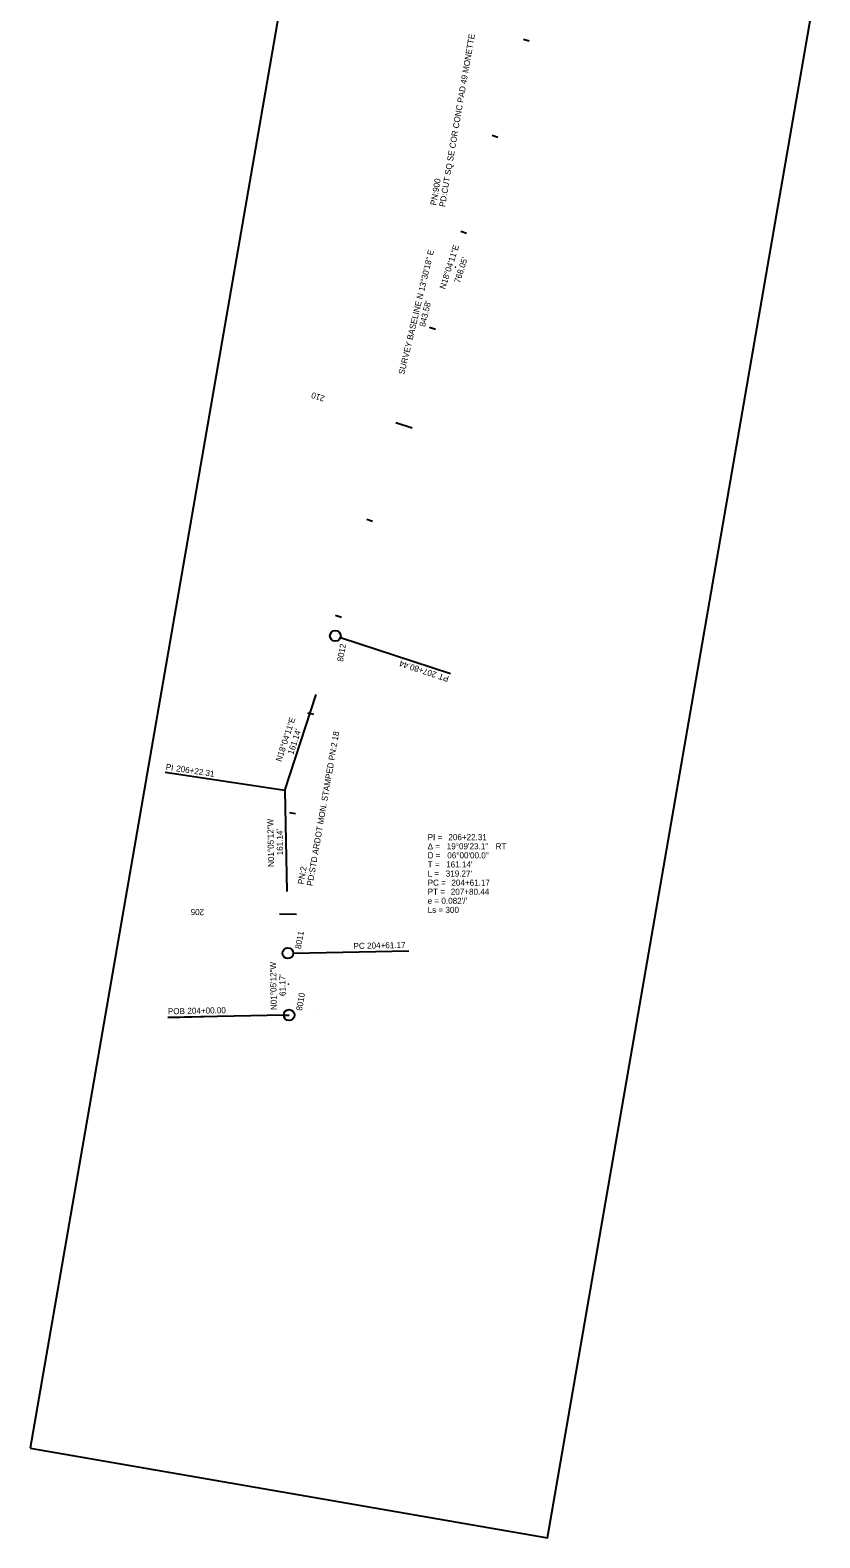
# Model space of a CAD drawing. Extents: x 1802363 to 1804577, y 572235 to 575339.
# Drawn here: x 1802947 to 1803729, y 572235 to 573728 of the extents above; entities that cross this region are included whole.
import ezdxf

# ---------------------------------------------------------------- set-up
doc = ezdxf.new("R2010")
doc.units = 0
for name, color, linetype in [('_CIVIL_CONSTRUCTION', 7, 'Continuous'), ('DSN_DRFT_Named-Boundary', 7, 'Continuous'), ('DSN_RDWY_Alignment Annotation', 7, 'Continuous'), ('DSN_ROW_Point-Annotation', 7, 'Continuous'), ('S_BASELINE_ANNOT', 7, 'Continuous'), ('S_PRIMARY_CTL_ANNOT', 7, 'Continuous')]:
    doc.layers.add(name, color=color, linetype=linetype)

msp = doc.modelspace()

# ---------------------------------------------------------------- linework, layer by layer
at = {"layer": '_CIVIL_CONSTRUCTION'}
for centre in [(1803368.1, 573493.4), (1803368.1, 573493.4), (1803368.1, 573493.4), (1803202.6, 572783.4)]:
    msp.add_circle(centre, 0.05, dxfattribs=at)
at = {"layer": 'DSN_DRFT_Named-Boundary'}
msp.add_line((1803231.8, 572753.4), (1803231.8, 572753.4), dxfattribs=at)
msp.add_lwpolyline([(1802946.7, 572323.9), (1803459.1, 572235.1), (1803729, 573792.9), (1803216.7, 573881.7)], close=True, dxfattribs=at)
at = {"layer": 'DSN_RDWY_Alignment Annotation'}
for p, q in [((1803435.4, 573719.1), (1803441.1, 573717.3)), ((1803404.4, 573624.1), (1803410.1, 573622.2)), ((1803373.4, 573529), (1803379.1, 573527.1)), ((1803342.4, 573433.9), (1803348.1, 573432.1)), ((1803309.1, 573339.6), (1803325, 573334.4)), ((1803280.3, 573243.8), (1803286, 573241.9)), ((1803249.3, 573148.7), (1803255, 573146.9)), ((1803249, 573128.3), (1803249, 573128.3)), ((1803254, 573126.6), (1803363, 573091.1)), ((1803363, 573091.1), (1803363, 573091.1)), ((1803199, 572975.1), (1803230, 573070.2)), ((1803221.4, 573052.2), (1803227.3, 573050.8)), ((1803199, 572975.1), (1803080.3, 572992.8)), ((1803080.3, 572992.8), (1803080.3, 572992.8)), ((1803199, 572975.1), (1803200.9, 572875.1)), ((1803203.5, 572953.2), (1803209.5, 572952.5)), ((1803193.7, 572853), (1803210.5, 572852.6)), ((1803202, 572814), (1803202, 572814)), ((1803207.4, 572814.1), (1803322, 572816.3)), ((1803322, 572816.3), (1803322, 572816.3)), ((1803197.9, 572752.7), (1803083.2, 572750.5)), ((1803083.2, 572750.5), (1803119.2, 572751.2)), ((1803197.2, 572752.7), (1803203.2, 572752.8)), ((1803203.2, 572752.8), (1803203.2, 572752.8))]:
    msp.add_line(p, q, dxfattribs=at)
for centre in [(1803249, 573128.3), (1803202, 572814), (1803203.2, 572752.8)]:
    msp.add_circle(centre, 5.34, dxfattribs=at)

# ---------------------------------------------------------------- texts
for s, rotation, p in [('N18°04\'11"E', 71.9303, (1803357.7, 573471.1)), ('210', 161.9303, (1803239.1, 573365.6)), ('8012', 80.1683, (1803256.6, 573102.4)), ('207+80.44', 161.9303, (1803349.8, 573092.2)), ('PT', 161.9303, (1803362.1, 573088.2)), ('N18°04\'11"E', 71.9303, (1803195.5, 573003.2)), ("161.14'", 71.9303, (1803207.3, 573010.2)), ('PI ', 351.5085, (1803080.7, 572995.8)), ('206+22.31', 351.5085, (1803091.1, 572994.2)), ('N01°05\'12"W', 91.0867, (1803188.4, 572899.5)), ("161.14'", 91.0867, (1803197.2, 572911)), ('205', 178.757, (1803119.1, 572857.6)), ('8011', 80.1683, (1803214.9, 572817.8)), ('204+61.17', 1.0867, (1803280.5, 572818.5)), ('PC', 1.0867, (1803267.1, 572818.2)), ('N01°05\'12"W', 91.0867, (1803191.1, 572757.8)), ("61.17'", 91.0867, (1803199.8, 572771.7)), ('8010', 80.1683, (1803216, 572756.7)), ('POB ', 1.0867, (1803083.2, 572753.5)), ('204+00.00', 1.0867, (1803102.5, 572753.9))]:
    msp.add_text(s, height=6, rotation=rotation, dxfattribs=at).set_placement(p)
for s, p in [('PI = ', (1803340.5, 572925.9)), ('206+22.31', (1803361, 572925.9)), ('Δ = ', (1803340.5, 572916.9)), ('19°09\'23.1"', (1803359.4, 572916.9)), (' RT', (1803405.6, 572916.9)), ('T = ', (1803340.5, 572898.9)), ('D = ', (1803340.5, 572907.9)), ("161.14'", (1803358.8, 572898.9)), ('06°00\'00.0"', (1803359.9, 572907.9)), ('L = ', (1803340.5, 572889.9)), ('PC = ', (1803340.5, 572880.9)), ("319.27'", (1803358.4, 572889.9)), ('204+61.17', (1803364, 572880.9)), ('PT = ', (1803340.5, 572871.9)), ('207+80.44', (1803363.4, 572871.9)), ("e = 0.082'/'", (1803340.5, 572862.9)), ('Ls = 300', (1803340.5, 572853.9))]:
    msp.add_text(s, height=6, dxfattribs=at).set_placement(p)
at = {"layer": 'DSN_ROW_Point-Annotation'}
msp.add_text("768.05'", height=6, rotation=71.9303, dxfattribs=at).set_placement((1803372.3, 573477.2))
at = {"layer": 'S_BASELINE_ANNOT'}
for s, p in [('SURVEY BASELINE N 13°30\'18" E', (1803317.3, 573386.6)), ("843.58'", (1803337.9, 573433.9))]:
    msp.add_text(s, height=6, rotation=76.495, dxfattribs=at).set_placement(p)
at = {"layer": 'S_PRIMARY_CTL_ANNOT'}
for s, p in [('PD:CUT SQ SE COR CONC PAD 49 MONETTE', (1803357.7, 573552.6)), ('PN:900', (1803348.9, 573554.2)), ('PD:STD ARDOT MON. STAMPED PN:2 18', (1803226.5, 572880.2)), ('PN:2', (1803217.6, 572881.8))]:
    msp.add_text(s, height=6, rotation=80.1683, dxfattribs=at).set_placement(p)

doc.saveas('drawing.dxf')
